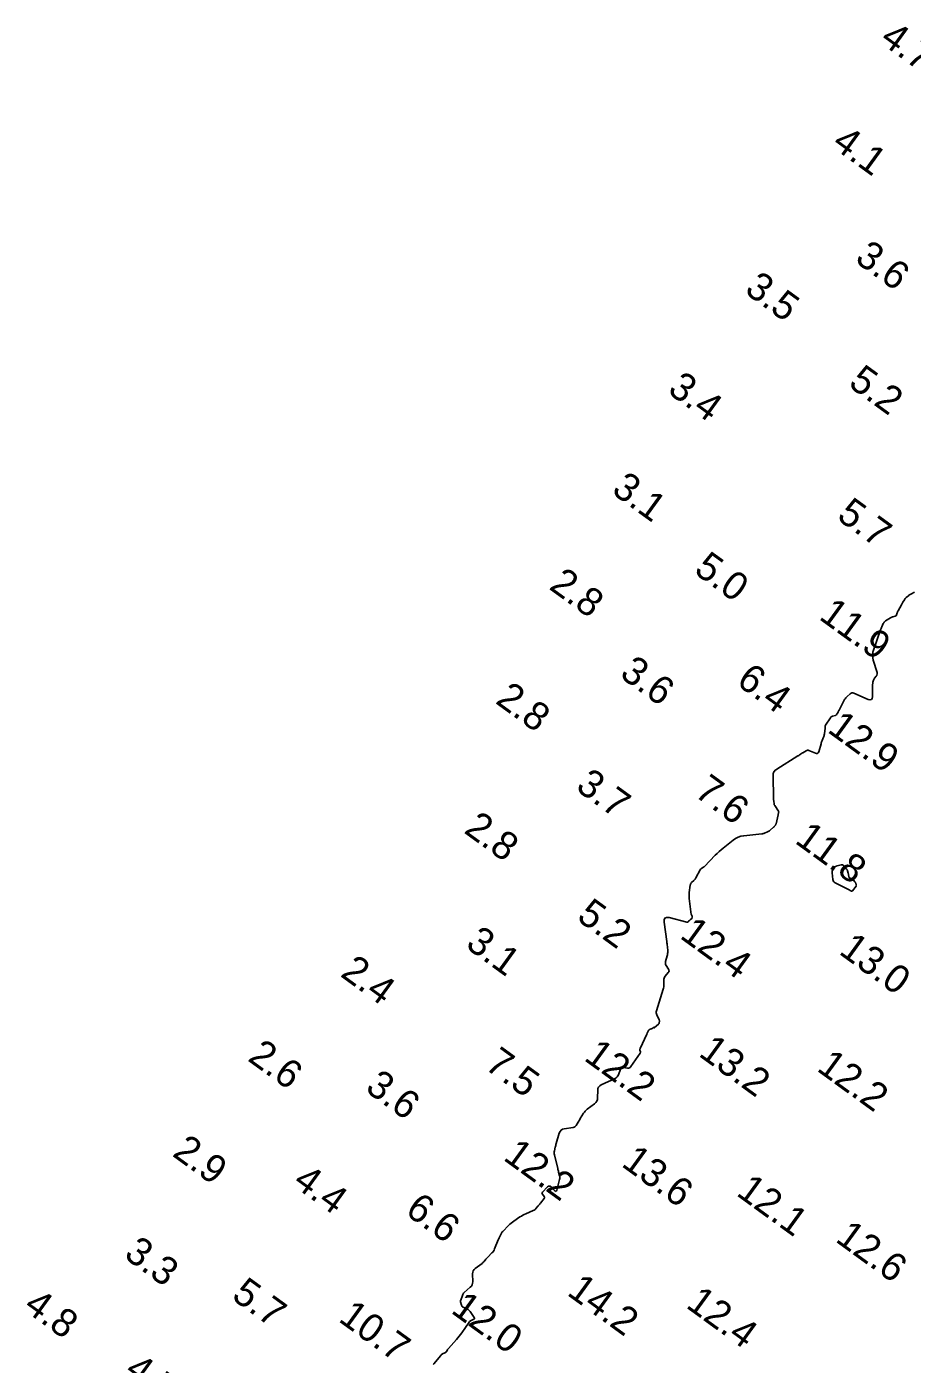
# Model space of a CAD drawing. Extents: x 815352 to 820877, y 582403 to 597439.
# Drawn here: x 818755.2 to 818912.9, y 587409 to 587647.2 of the extents above; entities that cross this region are included whole.
import ezdxf

# ---------------------------------------------------------------- set-up
doc = ezdxf.new("R2010")
doc.units = 0
doc.layers.add('V-CONT-EL12', color=7, linetype='Continuous')
doc.layers.add('V-TOPO-SOUN', color=7, linetype='Continuous')

msp = doc.modelspace()

# ---------------------------------------------------------------- linework, layer by layer
at = {"layer": 'V-CONT-EL12'}
msp.add_lwpolyline([(818827.61, 587408.96), (818827.71, 587409.07), (818828.95, 587410.58), (818829.02, 587410.65), (818829.09, 587410.72), (818829.18, 587410.78), (818829.27, 587410.83), (818829.68, 587411.03), (818829.75, 587411.07), (818829.82, 587411.12), (818829.88, 587411.18), (818829.93, 587411.25), (818830.11, 587411.54), (818830.15, 587411.61), (818830.2, 587411.68), (818830.26, 587411.74), (818830.31, 587411.81), (818831.74, 587413.4), (818831.99, 587413.69), (818832.23, 587413.99), (818832.46, 587414.29), (818832.68, 587414.6), (818833.98, 587416.49), (818834.06, 587416.59), (818834.15, 587416.68), (818834.25, 587416.75), (818834.36, 587416.81), (818834.82, 587417.02), (818834.92, 587417.07), (818834.96, 587417.15), (818834.96, 587417.23), (818834.91, 587417.33), (818834.19, 587418.37), (818834.08, 587418.5), (818833.96, 587418.62), (818833.82, 587418.72), (818833.67, 587418.81), (818832.93, 587419.16), (818832.83, 587419.22), (818832.75, 587419.29), (818832.69, 587419.39), (818832.65, 587419.49), (818832.45, 587420.13), (818832.44, 587420.15), (818832.44, 587420.18), (818832.44, 587420.2), (818832.44, 587420.22), (818832.46, 587420.31), (818832.47, 587420.33), (818832.48, 587420.36), (818832.48, 587420.38), (818832.49, 587420.4), (818832.78, 587421.26), (818832.84, 587421.41), (818832.91, 587421.54), (818833.01, 587421.66), (818833.12, 587421.78), (818834.19, 587422.72), (818834.38, 587422.92), (818834.51, 587423.15), (818834.6, 587423.41), (818834.62, 587423.69), (818834.61, 587425.09), (818834.64, 587425.37), (818834.72, 587425.62), (818834.87, 587425.84), (818835.07, 587426.04), (818836.28, 587426.96), (818836.38, 587427.04), (818836.47, 587427.12), (818836.56, 587427.21), (818836.64, 587427.3), (818836.97, 587427.68), (818837.05, 587427.78), (818837.13, 587427.87), (818837.22, 587427.96), (818837.3, 587428.05), (818838.05, 587428.81), (818838.19, 587428.97), (818838.32, 587429.15), (818838.43, 587429.34), (818838.52, 587429.53), (818839.15, 587431.13), (818839.16, 587431.17), (818839.18, 587431.21), (818839.2, 587431.26), (818839.22, 587431.3), (818839.31, 587431.46), (818839.33, 587431.5), (818839.35, 587431.55), (818839.37, 587431.59), (818839.39, 587431.63), (818839.68, 587432.23), (818839.74, 587432.34), (818839.8, 587432.45), (818839.88, 587432.55), (818839.96, 587432.64), (818841.02, 587433.73), (818841.23, 587433.94), (818841.45, 587434.13), (818841.68, 587434.31), (818841.92, 587434.48), (818843.04, 587435.23), (818843.29, 587435.39), (818843.54, 587435.53), (818843.8, 587435.67), (818844.07, 587435.79), (818845.4, 587436.37), (818845.54, 587436.44), (818845.66, 587436.52), (818845.78, 587436.62), (818845.89, 587436.74), (818846.29, 587437.21), (818846.39, 587437.33), (818846.49, 587437.46), (818846.59, 587437.58), (818846.68, 587437.7), (818847.32, 587438.51), (818847.38, 587438.6), (818847.4, 587438.7), (818847.38, 587438.79), (818847.32, 587438.89), (818847.03, 587439.27), (818846.98, 587439.37), (818846.96, 587439.46), (818846.99, 587439.55), (818847.05, 587439.64), (818847.95, 587440.57), (818848.11, 587440.69), (818848.27, 587440.73), (818848.42, 587440.69), (818848.57, 587440.56), (818849.19, 587439.91), (818849.33, 587439.8), (818849.45, 587439.78), (818849.54, 587439.85), (818849.61, 587440.02), (818850.1, 587441.92), (818850.13, 587442.08), (818850.14, 587442.25), (818850.13, 587442.41), (818850.1, 587442.57), (818849.92, 587443.21), (818849.88, 587443.37), (818849.83, 587443.53), (818849.79, 587443.69), (818849.75, 587443.85), (818849.16, 587446.3), (818849.13, 587446.47), (818849.12, 587446.63), (818849.13, 587446.8), (818849.16, 587446.97), (818849.32, 587447.63), (818849.36, 587447.8), (818849.4, 587447.97), (818849.45, 587448.13), (818849.49, 587448.3), (818850.04, 587450.17), (818850.17, 587450.46), (818850.35, 587450.68), (818850.59, 587450.83), (818850.88, 587450.91), (818852.5, 587451.17), (818852.66, 587451.21), (818852.81, 587451.28), (818852.93, 587451.39), (818853.03, 587451.52), (818853.4, 587452.13), (818853.49, 587452.28), (818853.59, 587452.43), (818853.68, 587452.59), (818853.77, 587452.74), (818854.37, 587453.69), (818854.51, 587453.89), (818854.66, 587454.07), (818854.84, 587454.24), (818855.02, 587454.4), (818856.31, 587455.37), (818856.55, 587455.58), (818856.72, 587455.84), (818856.82, 587456.12), (818856.86, 587456.44), (818856.88, 587457.79), (818856.92, 587458.1), (818857.04, 587458.36), (818857.23, 587458.58), (818857.5, 587458.74), (818859.98, 587459.9), (818860.18, 587460.02), (818860.34, 587460.16), (818860.47, 587460.34), (818860.57, 587460.55), (818860.91, 587461.53), (818860.99, 587461.69), (818861.1, 587461.79), (818861.24, 587461.84), (818861.42, 587461.84), (818862.19, 587461.73), (818862.37, 587461.73), (818862.53, 587461.77), (818862.67, 587461.86), (818862.79, 587462), (818864.42, 587464.39), (818864.45, 587464.45), (818864.47, 587464.51), (818864.48, 587464.58), (818864.47, 587464.65), (818864.4, 587464.94), (818864.39, 587465.01), (818864.4, 587465.08), (818864.41, 587465.15), (818864.43, 587465.22), (818865.6, 587467.75), (818865.64, 587467.83), (818865.67, 587467.91), (818865.71, 587467.99), (818865.75, 587468.07), (818865.91, 587468.41), (818865.95, 587468.47), (818865.99, 587468.52), (818866.05, 587468.56), (818866.11, 587468.59), (818866.42, 587468.71), (818866.46, 587468.73), (818866.5, 587468.75), (818866.54, 587468.77), (818866.57, 587468.8), (818866.76, 587468.93), (818866.78, 587468.94), (818866.8, 587468.95), (818866.82, 587468.95), (818866.84, 587468.94), (818866.93, 587468.92), (818866.95, 587468.92), (818866.97, 587468.92), (818866.99, 587468.93), (818867.01, 587468.94), (818867.72, 587469.57), (818867.76, 587469.62), (818867.8, 587469.68), (818867.82, 587469.74), (818867.83, 587469.8), (818867.86, 587470.07), (818867.87, 587470.14), (818867.86, 587470.2), (818867.84, 587470.27), (818867.82, 587470.33), (818867.38, 587471.24), (818867.32, 587471.41), (818867.29, 587471.58), (818867.29, 587471.76), (818867.33, 587471.94), (818868.54, 587475.79), (818868.59, 587475.98), (818868.63, 587476.18), (818868.65, 587476.38), (818868.65, 587476.58), (818868.63, 587477.39), (818868.65, 587477.58), (818868.69, 587477.77), (818868.78, 587477.94), (818868.89, 587478.1), (818869.44, 587478.74), (818869.54, 587478.89), (818869.58, 587479.04), (818869.56, 587479.2), (818869.49, 587479.36), (818869.06, 587480.02), (818868.97, 587480.19), (818868.93, 587480.36), (818868.92, 587480.54), (818868.96, 587480.73), (818869.25, 587481.71), (818869.3, 587481.92), (818869.33, 587482.13), (818869.35, 587482.34), (818869.34, 587482.55), (818869.28, 587483.4), (818869.26, 587483.62), (818869.24, 587483.83), (818869.21, 587484.04), (818869.18, 587484.26), (818868.69, 587487.69), (818868.69, 587488.16), (818868.84, 587488.45), (818869.15, 587488.57), (818869.61, 587488.52), (818872.73, 587487.72), (818872.8, 587487.71), (818872.86, 587487.72), (818872.91, 587487.74), (818872.97, 587487.78), (818873.16, 587487.99), (818873.21, 587488.04), (818873.26, 587488.09), (818873.32, 587488.13), (818873.38, 587488.17), (818873.65, 587488.37), (818873.69, 587488.41), (818873.72, 587488.45), (818873.73, 587488.49), (818873.72, 587488.55), (818873.67, 587488.82), (818873.66, 587488.85), (818873.65, 587488.87), (818873.64, 587488.89), (818873.63, 587488.92), (818873.57, 587489), (818873.56, 587489.02), (818873.55, 587489.05), (818873.54, 587489.07), (818873.53, 587489.1), (818873.18, 587491.91), (818873.15, 587492.17), (818873.14, 587492.44), (818873.15, 587492.71), (818873.18, 587492.98), (818873.34, 587494.31), (818873.37, 587494.44), (818873.42, 587494.56), (818873.49, 587494.68), (818873.59, 587494.78), (818874.01, 587495.15), (818874.11, 587495.25), (818874.2, 587495.35), (818874.28, 587495.47), (818874.36, 587495.59), (818875.12, 587497.06), (818875.16, 587497.13), (818875.21, 587497.19), (818875.27, 587497.25), (818875.34, 587497.29), (818875.62, 587497.45), (818875.69, 587497.49), (818875.76, 587497.54), (818875.82, 587497.59), (818875.88, 587497.65), (818877.79, 587499.62), (818878.14, 587499.97), (818878.49, 587500.3), (818878.86, 587500.62), (818879.23, 587500.92), (818880.98, 587502.31), (818881.42, 587502.61), (818881.88, 587502.84), (818882.37, 587503), (818882.88, 587503.1), (818886.07, 587503.44), (818886.2, 587503.46), (818886.33, 587503.49), (818886.46, 587503.53), (818886.59, 587503.57), (818887.09, 587503.78), (818887.21, 587503.84), (818887.33, 587503.91), (818887.44, 587503.98), (818887.55, 587504.07), (818888.18, 587504.61), (818888.23, 587504.65), (818888.28, 587504.7), (818888.32, 587504.74), (818888.36, 587504.8), (818888.51, 587505.01), (818888.55, 587505.06), (818888.58, 587505.12), (818888.6, 587505.18), (818888.62, 587505.24), (818888.98, 587506.8), (818888.99, 587506.86), (818889.01, 587506.92), (818889.02, 587506.98), (818889.04, 587507.04), (818889.09, 587507.27), (818889.1, 587507.33), (818889.1, 587507.39), (818889.08, 587507.44), (818889.06, 587507.49), (818888.4, 587508.47), (818888.36, 587508.54), (818888.32, 587508.62), (818888.3, 587508.7), (818888.29, 587508.78), (818888.26, 587509.28), (818888.26, 587509.28), (818888.25, 587509.29), (818888.25, 587509.3), (818888.25, 587509.3), (818888.23, 587509.33), (818888.22, 587509.33), (818888.22, 587509.34), (818888.22, 587509.35), (818888.22, 587509.35), (818888.19, 587509.46), (818888.19, 587509.48), (818888.18, 587509.5), (818888.18, 587509.52), (818888.18, 587509.54), (818888.1, 587514.02), (818888.11, 587514.11), (818888.13, 587514.2), (818888.16, 587514.28), (818888.2, 587514.36), (818888.48, 587514.77), (818888.5, 587514.8), (818888.52, 587514.82), (818888.54, 587514.84), (818888.57, 587514.85), (818888.68, 587514.9), (818888.7, 587514.91), (818888.73, 587514.92), (818888.76, 587514.94), (818888.78, 587514.96), (818892.52, 587517.31), (818892.59, 587517.36), (818892.66, 587517.4), (818892.74, 587517.45), (818892.81, 587517.5), (818893.1, 587517.7), (818893.17, 587517.75), (818893.24, 587517.79), (818893.31, 587517.84), (818893.39, 587517.88), (818893.98, 587518.24), (818894.11, 587518.3), (818894.23, 587518.32), (818894.36, 587518.32), (818894.49, 587518.28), (818895.63, 587517.78), (818895.84, 587517.72), (818896.01, 587517.75), (818896.14, 587517.86), (818896.23, 587518.07), (818896.63, 587519.47), (818896.67, 587519.62), (818896.72, 587519.77), (818896.77, 587519.92), (818896.83, 587520.06), (818897.07, 587520.64), (818897.12, 587520.78), (818897.17, 587520.93), (818897.2, 587521.08), (818897.23, 587521.23), (818897.38, 587522.28), (818897.39, 587522.32), (818897.39, 587522.37), (818897.39, 587522.41), (818897.39, 587522.45), (818897.39, 587522.63), (818897.39, 587522.67), (818897.4, 587522.71), (818897.42, 587522.75), (818897.44, 587522.79), (818898.3, 587524.12), (818898.37, 587524.21), (818898.46, 587524.29), (818898.56, 587524.35), (818898.67, 587524.39), (818899.19, 587524.54), (818899.28, 587524.58), (818899.35, 587524.63), (818899.42, 587524.69), (818899.47, 587524.77), (818899.66, 587525.12), (818899.7, 587525.21), (818899.75, 587525.3), (818899.8, 587525.39), (818899.84, 587525.48), (818900.82, 587527.34), (818900.91, 587527.49), (818901.02, 587527.64), (818901.14, 587527.78), (818901.27, 587527.91), (818901.84, 587528.39), (818901.99, 587528.49), (818902.14, 587528.53), (818902.31, 587528.53), (818902.47, 587528.48), (818905.03, 587527.38), (818905.36, 587527.29), (818905.59, 587527.34), (818905.73, 587527.53), (818905.78, 587527.86), (818905.82, 587530.08), (818905.83, 587530.17), (818905.84, 587530.27), (818905.86, 587530.36), (818905.88, 587530.45), (818906, 587530.83), (818906.03, 587530.92), (818906.07, 587531), (818906.12, 587531.08), (818906.17, 587531.16), (818906.45, 587531.5), (818906.48, 587531.55), (818906.51, 587531.6), (818906.54, 587531.66), (818906.56, 587531.71), (818906.63, 587531.94), (818906.64, 587531.99), (818906.65, 587532.05), (818906.64, 587532.11), (818906.63, 587532.17), (818905.93, 587534.39), (818905.92, 587534.45), (818905.9, 587534.51), (818905.89, 587534.56), (818905.88, 587534.62), (818905.86, 587534.85), (818905.85, 587534.91), (818905.85, 587534.97), (818905.84, 587535.03), (818905.84, 587535.09), (818905.84, 587535.57), (818905.85, 587535.67), (818905.86, 587535.77), (818905.88, 587535.86), (818905.91, 587535.96), (818907.22, 587539.74), (818907.27, 587539.88), (818907.33, 587540.03), (818907.39, 587540.18), (818907.46, 587540.32), (818907.72, 587540.9), (818907.8, 587541.04), (818907.89, 587541.16), (818908, 587541.26), (818908.12, 587541.36), (818909.02, 587541.92), (818909.12, 587541.97), (818909.21, 587542.02), (818909.31, 587542.06), (818909.41, 587542.09), (818909.83, 587542.2), (818909.92, 587542.24), (818909.99, 587542.29), (818910.04, 587542.35), (818910.08, 587542.44), (818910.19, 587542.8), (818910.22, 587542.89), (818910.26, 587542.98), (818910.3, 587543.07), (818910.34, 587543.15), (818910.96, 587544.21), (818911.02, 587544.33), (818911.09, 587544.44), (818911.15, 587544.55), (818911.22, 587544.67), (818911.47, 587545.13), (818911.54, 587545.23), (818911.61, 587545.33), (818911.7, 587545.43), (818911.79, 587545.51), (818912.18, 587545.84), (818912.28, 587545.92), (818912.38, 587545.99), (818912.49, 587546.06), (818912.6, 587546.12), (818913.27, 587546.48)], dxfattribs=at)
msp.add_lwpolyline([(818902.92, 587494.29), (818902.91, 587494.23), (818902.89, 587494.17), (818902.86, 587494.11), (818902.21, 587493.3), (818902.17, 587493.26), (818902.13, 587493.25), (818902.08, 587493.25), (818902.03, 587493.26), (818901.83, 587493.37), (818901.77, 587493.4), (818901.72, 587493.43), (818901.67, 587493.45), (818901.62, 587493.48), (818899.16, 587494.72), (818898.99, 587494.83), (818898.87, 587494.97), (818898.78, 587495.14), (818898.74, 587495.34), (818898.64, 587496.52), (818898.63, 587496.57), (818898.63, 587496.61), (818898.63, 587496.66), (818898.63, 587496.7), (818898.64, 587496.88), (818898.64, 587496.93), (818898.65, 587496.97), (818898.66, 587497.02), (818898.67, 587497.06), (818898.79, 587497.37), (818898.82, 587497.43), (818898.86, 587497.48), (818898.91, 587497.52), (818898.97, 587497.55), (818899.23, 587497.65), (818899.29, 587497.68), (818899.36, 587497.7), (818899.43, 587497.72), (818899.5, 587497.74), (818900.2, 587497.91), (818900.34, 587497.92), (818900.46, 587497.9), (818900.57, 587497.85), (818900.67, 587497.76), (818901.19, 587497.16), (818901.24, 587497.09), (818901.29, 587497.01), (818901.33, 587496.93), (818901.35, 587496.85), (818901.46, 587496.47), (818901.48, 587496.39), (818901.5, 587496.32), (818901.51, 587496.24), (818901.52, 587496.16), (818901.56, 587495.85), (818901.58, 587495.77), (818901.62, 587495.71), (818901.66, 587495.66), (818901.73, 587495.61), (818902.18, 587495.38), (818902.25, 587495.33), (818902.32, 587495.29), (818902.38, 587495.23), (818902.44, 587495.17), (818902.68, 587494.88), (818902.73, 587494.83), (818902.76, 587494.77), (818902.79, 587494.7), (818902.82, 587494.64), (818902.9, 587494.36)], close=True, dxfattribs=at)

# ---------------------------------------------------------------- texts
at = {"layer": 'V-TOPO-SOUN'}
for s, p in [('4.7', (818906.91, 587644.44)), ('4.1', (818898.36, 587625.86)), ('3.6', (818902.45, 587605.44)), ('3.5', (818882.82, 587599.89)), ('5.2', (818901.3, 587583.25)), ('3.4', (818869.12, 587582.07)), ('3.1', (818859.15, 587564.22)), ('5.7', (818899.24, 587559.6)), ('5.0', (818873.81, 587550)), ('2.8', (818848.02, 587547.16)), ('11.9 ', (818896.07, 587541.8)), ('3.6', (818860.59, 587531.49)), ('6.4', (818881.36, 587530.14)), ('2.8', (818838.48, 587526.82)), ('12.9 ', (818897.58, 587521.69)), ('3.7', (818852.75, 587511.4)), ('7.6', (818873.88, 587510.33)), ('2.8', (818832.87, 587503.76)), ('11.8 ', (818891.78, 587501.94)), ('5.2', (818852.94, 587488.24)), ('3.1', (818833.14, 587483.34)), ('12.4 ', (818871.3, 587485.01)), ('13.0 ', (818899.62, 587482.2)), ('2.4', (818810.88, 587478.2)), ('13.2 ', (818874.65, 587464.02)), ('2.6', (818794.38, 587463.18)), ('7.5', (818836.56, 587461.76)), ('12.2 ', (818854.24, 587463.26)), ('12.2 ', (818895.68, 587461.39)), ('3.6', (818815.28, 587457.77)), ('2.9', (818780.96, 587446.21)), ('12.2 ', (818839.87, 587445.51)), ('13.6 ', (818860.91, 587444.39)), ('4.4', (818802.39, 587440.93)), ('12.1 ', (818881.36, 587439.2)), ('6.6', (818822.4, 587435.85)), ('12.6 ', (818899, 587430.97)), ('3.3', (818772.33, 587428.1)), ('5.7', (818791.49, 587420.75)), ('14.2 ', (818851.22, 587421.46)), ('4.8', (818754.45, 587418.79)), ('12.4 ', (818872.39, 587419.23)), ('10.7 ', (818810.54, 587416.77)), ('12.0 ', (818830.56, 587418.29)), ('4.7', (818772.43, 587407.24))]:
    msp.add_text(s, height=5, rotation=324, dxfattribs=at).set_placement(p)

doc.saveas('drawing.dxf')
